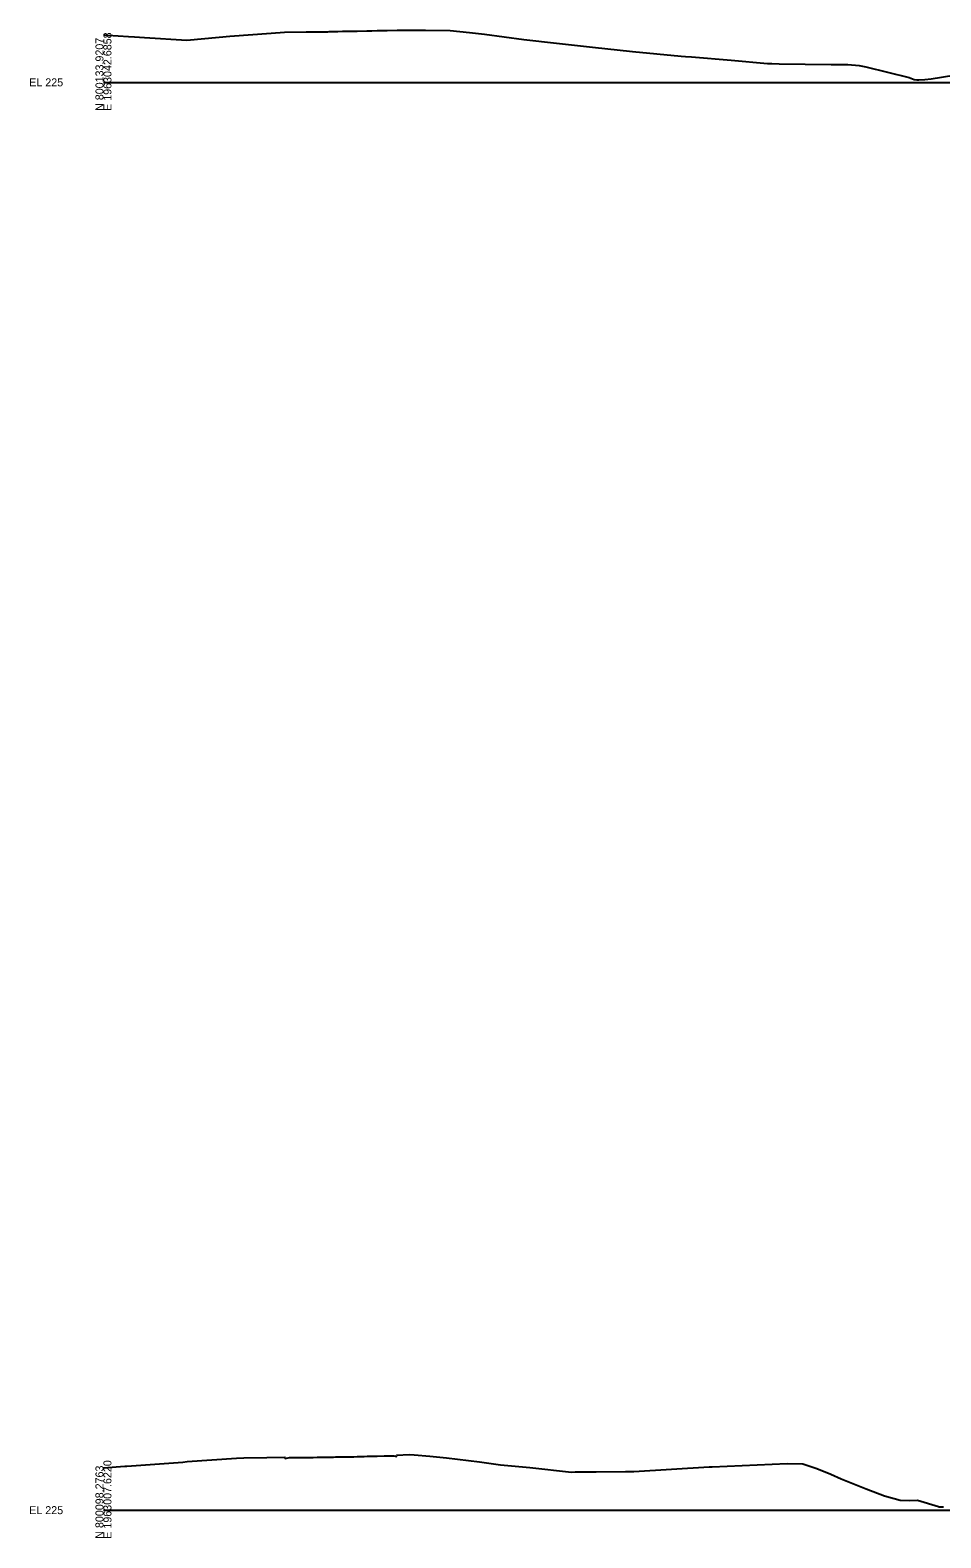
# Model space of a CAD drawing. Extents: x -4026 to 9638, y -10 to 19609.
# Drawn here: x 1974 to 2293, y 3990 to 4518 of the extents above; entities that cross this region are included whole.
import ezdxf

# ---------------------------------------------------------------- set-up
doc = ezdxf.new("R2010")
doc.units = 0
for name, color, linetype in [('Default', 7, 'Continuous'), ('RD_GPK_XS_Cell', 7, 'Continuous'), ('RD_XS_ExGround', 7, 'Continuous')]:
    doc.layers.add(name, color=color, linetype=linetype)

msp = doc.modelspace()

# ---------------------------------------------------------------- linework, layer by layer
at = {"layer": 'RD_GPK_XS_Cell'}
for p, q in [((2000, 4500), (2350, 4500)), ((2000, 4000), (2350, 4000))]:
    msp.add_line(p, q, dxfattribs=at)
at = {"layer": 'RD_XS_ExGround'}
for points in [[(2000, 4516.68), (2001.53, 4516.56), (2008.77, 4516.03), (2010.84, 4515.88), (2014.34, 4515.69), (2029.22, 4514.77), (2040.51, 4515.78), (2044.32, 4516.17), (2058.72, 4517.25), (2063.39, 4517.53), (2071.08, 4517.64), (2071.68, 4517.65), (2073.48, 4517.67), (2078.67, 4517.73), (2079.15, 4517.75), (2079.95, 4517.77), (2081.77, 4517.81), (2082.17, 4517.82), (2083.79, 4517.87), (2085.37, 4517.9), (2087.01, 4517.94), (2088.88, 4517.98), (2092.35, 4518.05), (2094.1, 4518.08), (2095.88, 4518.1), (2097.33, 4518.13), (2099.39, 4518.18), (2102.94, 4518.22), (2104.67, 4518.24), (2106.49, 4518.25), (2108.2, 4518.27), (2110.08, 4518.28), (2110.38, 4518.28), (2112.84, 4518.27), (2112.87, 4518.27), (2121.48, 4518.13), (2128.27, 4517.47), (2133.51, 4516.93), (2147.37, 4515.06), (2158.77, 4513.67), (2171.35, 4512.32), (2185.42, 4510.8), (2202.42, 4509.2), (2203.93, 4509.07), (2206.09, 4508.89), (2219.96, 4507.77), (2232.74, 4506.62), (2234.23, 4506.58), (2236.77, 4506.53), (2255.04, 4506.23), (2260.91, 4506.29), (2264.87, 4505.92), (2267.15, 4505.45), (2282.31, 4501.64), (2284.13, 4500.99), (2285.02, 4500.93), (2285.78, 4500.93), (2287.83, 4500.94), (2290.1, 4501.18), (2298.05, 4502.52)], [(2000, 4014.78), (2007.51, 4015.37), (2008.21, 4015.43), (2027.85, 4016.86), (2029.35, 4016.99), (2046.64, 4018.19), (2049.2, 4018.35), (2057.25, 4018.45), (2063.56, 4018.53), (2063.67, 4018.08), (2065.21, 4018.39), (2066.48, 4018.4), (2067.65, 4018.41), (2068.19, 4018.42), (2068.92, 4018.43), (2069.99, 4018.44), (2071.36, 4018.45), (2072.44, 4018.47), (2073.53, 4018.5), (2074.94, 4018.52), (2075.99, 4018.54), (2077.07, 4018.56), (2078.42, 4018.58), (2079.53, 4018.6), (2080.67, 4018.61), (2081.32, 4018.62), (2081.95, 4018.63), (2084.25, 4018.66), (2084.85, 4018.67), (2085.43, 4018.68), (2087.79, 4018.73), (2088.92, 4018.75), (2091.32, 4018.83), (2092.42, 4018.86), (2093.65, 4018.89), (2094.9, 4018.91), (2095.42, 4018.92), (2095.93, 4018.93), (2098.43, 4018.97), (2099.43, 4018.99), (2101.82, 4019.03), (2102.73, 4018.82), (2102.84, 4019.26), (2107.16, 4019.45), (2108.85, 4019.39), (2114.34, 4018.91), (2120.24, 4018.31), (2131.8, 4016.87), (2139.19, 4015.91), (2149.39, 4014.93), (2164.05, 4013.35), (2165.33, 4013.38), (2172.66, 4013.42), (2182.94, 4013.51), (2185.88, 4013.52), (2212.22, 4015.13), (2213.32, 4015.17), (2239.58, 4016.4), (2245.09, 4016.25), (2249.95, 4014.55), (2254.94, 4012.63), (2258.48, 4010.95), (2267.3, 4007.47), (2273.73, 4005.04), (2279.16, 4003.56), (2282.49, 4003.42), (2285.3, 4003.54), (2292.62, 4001.24), (2292.87, 4001.2), (2294.42, 4001.18)]]:
    msp.add_lwpolyline(points, dxfattribs=at)

# ---------------------------------------------------------------- texts
at = {"layer": 'Default'}
for p in [(2000, 4500), (2000, 4000)]:
    msp.add_text('-', height=0.0001, dxfattribs=at).set_placement(p)
at = {"layer": 'RD_GPK_XS_Cell'}
for s, p in [('N 800133.9207', (2000, 4490)), ('E 1963042.6858', (2002.8, 4490)), ('N 800098.2763', (2000, 3990)), ('E 1963007.6220', (2002.8, 3990))]:
    msp.add_text(s, height=2.8, rotation=90, dxfattribs=at).set_placement(p)
for p in [(1974, 4498.6), (1974, 3998.6)]:
    msp.add_text('EL 225', height=2.8, dxfattribs=at).set_placement(p)

doc.saveas('drawing.dxf')
